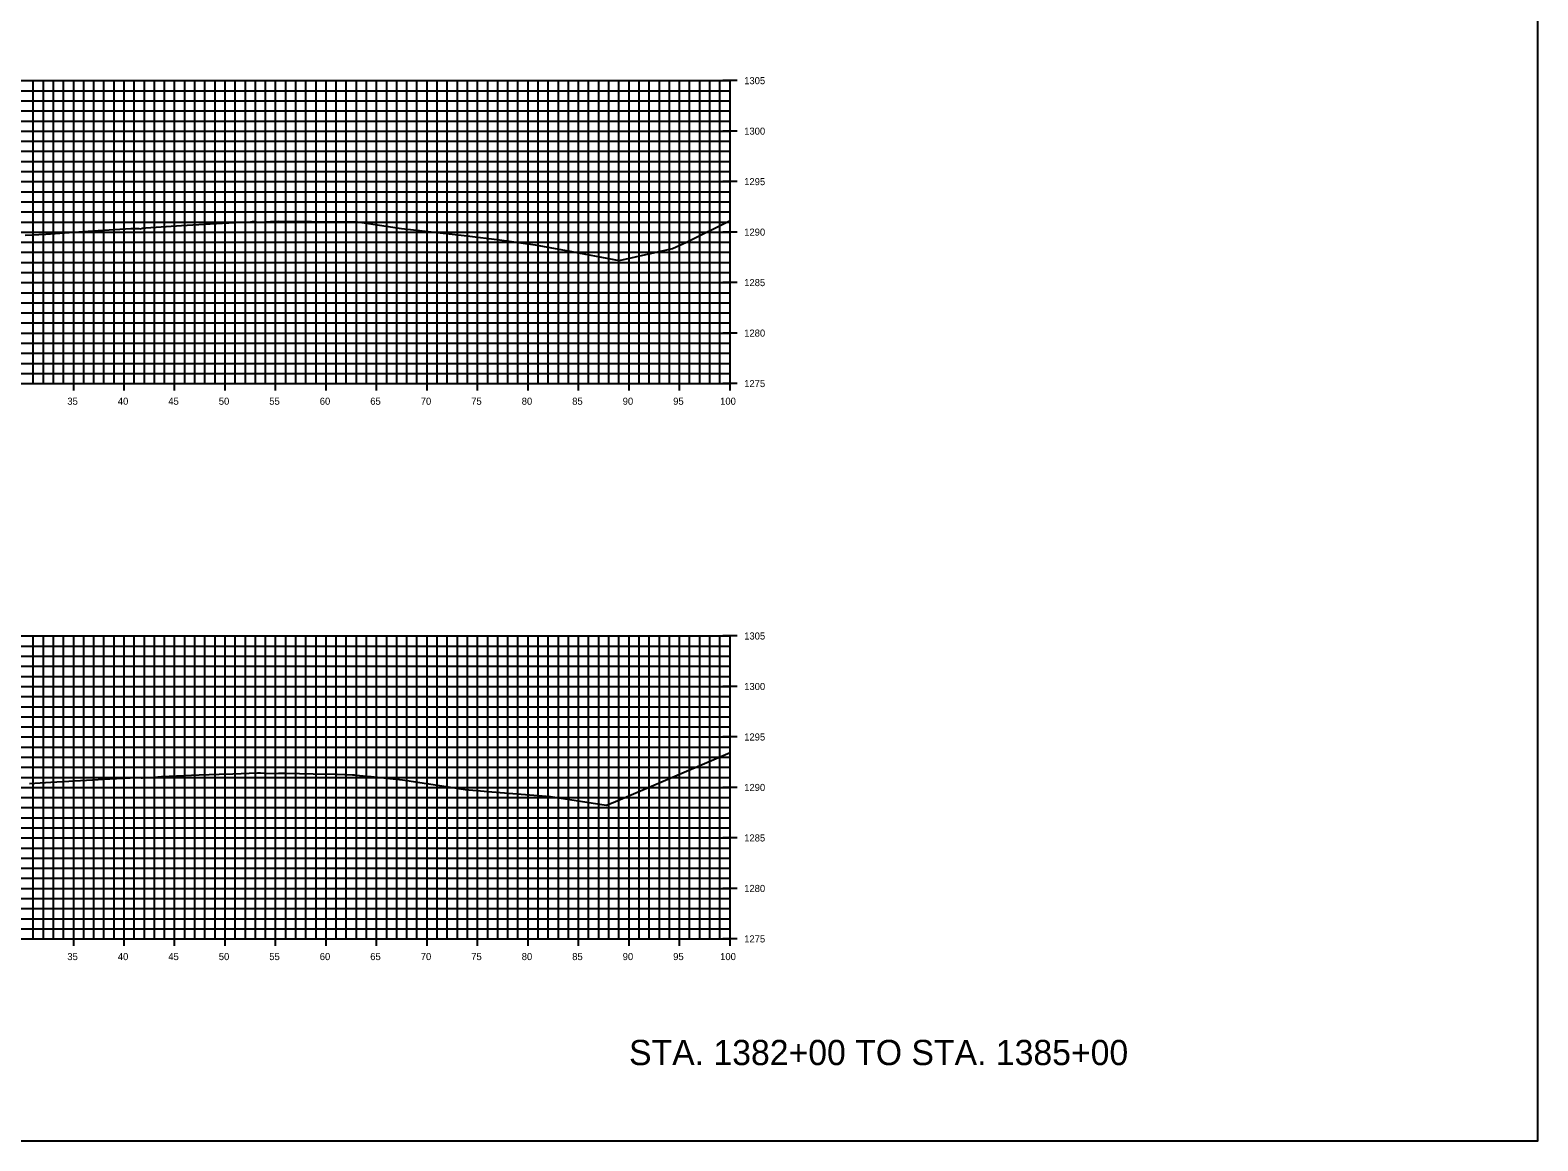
# Model space of a CAD drawing. Extents: x 674939 to 678919, y 750652 to 765176.
# Drawn here: x 678769.2 to 678918.5, y 755292.6 to 755402.6 of the extents above; entities that cross this region are included whole.
import ezdxf

# ---------------------------------------------------------------- set-up
doc = ezdxf.new("R2010")
doc.units = 0
for name, color, linetype in [('R_Axis', 7, 'Continuous'), ('R_Axis Annot', 7, 'Continuous'), ('R_Draft', 7, 'Continuous'), ('R_Exist Surface', 7, 'Continuous'), ('R_Grid', 7, 'Continuous'), ('R_No Plot', 7, 'Continuous')]:
    doc.layers.add(name, color=color, linetype=linetype)

msp = doc.modelspace()

# ---------------------------------------------------------------- linework, layer by layer
at = {"layer": 'R_Axis'}
for p, q in [((678839.23, 755397.55), (678837.83, 755397.55)), ((678838.53, 755367.55), (678838.53, 755397.55)), ((678839.23, 755392.55), (678837.83, 755392.55)), ((678839.23, 755387.55), (678837.83, 755387.55)), ((678839.23, 755382.55), (678837.83, 755382.55)), ((678839.23, 755377.55), (678837.83, 755377.55)), ((678839.23, 755372.55), (678837.83, 755372.55)), ((678638.53, 755367.55), (678838.53, 755367.55)), ((678773.53, 755366.85), (678773.53, 755368.25)), ((678778.53, 755366.85), (678778.53, 755368.25)), ((678783.53, 755366.85), (678783.53, 755368.25)), ((678788.53, 755366.85), (678788.53, 755368.25)), ((678793.53, 755366.85), (678793.53, 755368.25)), ((678798.53, 755366.85), (678798.53, 755368.25)), ((678803.53, 755366.85), (678803.53, 755368.25)), ((678808.53, 755366.85), (678808.53, 755368.25)), ((678813.53, 755366.85), (678813.53, 755368.25)), ((678818.53, 755366.85), (678818.53, 755368.25)), ((678823.53, 755366.85), (678823.53, 755368.25)), ((678828.53, 755366.85), (678828.53, 755368.25)), ((678833.53, 755366.85), (678833.53, 755368.25)), ((678839.23, 755367.55), (678837.83, 755367.55)), ((678838.53, 755366.85), (678838.53, 755368.25)), ((678839.23, 755342.55), (678837.83, 755342.55)), ((678838.53, 755312.55), (678838.53, 755342.55)), ((678839.23, 755337.55), (678837.83, 755337.55)), ((678839.23, 755332.55), (678837.83, 755332.55)), ((678839.23, 755327.55), (678837.83, 755327.55)), ((678839.23, 755322.55), (678837.83, 755322.55)), ((678839.23, 755317.55), (678837.83, 755317.55)), ((678638.53, 755312.55), (678838.53, 755312.55)), ((678773.53, 755311.85), (678773.53, 755313.25)), ((678778.53, 755311.85), (678778.53, 755313.25)), ((678783.53, 755311.85), (678783.53, 755313.25)), ((678788.53, 755311.85), (678788.53, 755313.25)), ((678793.53, 755311.85), (678793.53, 755313.25)), ((678798.53, 755311.85), (678798.53, 755313.25)), ((678803.53, 755311.85), (678803.53, 755313.25)), ((678808.53, 755311.85), (678808.53, 755313.25)), ((678813.53, 755311.85), (678813.53, 755313.25)), ((678818.53, 755311.85), (678818.53, 755313.25)), ((678823.53, 755311.85), (678823.53, 755313.25)), ((678828.53, 755311.85), (678828.53, 755313.25)), ((678833.53, 755311.85), (678833.53, 755313.25)), ((678839.23, 755312.55), (678837.83, 755312.55)), ((678838.53, 755311.85), (678838.53, 755313.25))]:
    msp.add_line(p, q, dxfattribs=at)
at = {"layer": 'R_Exist Surface'}
for points in [[(678768.72, 755382.24), (678770.09, 755382.32), (678770.77, 755382.36), (678775.43, 755382.66), (678779.19, 755382.9), (678779.53, 755382.9), (678779.99, 755382.9), (678780.1, 755382.89), (678780.33, 755382.94), (678780.67, 755382.97), (678784.22, 755383.19), (678787.04, 755383.36), (678789.53, 755383.49), (678791.06, 755383.58), (678791.23, 755383.59), (678791.39, 755383.59), (678791.64, 755383.57), (678791.99, 755383.55), (678793.02, 755383.59), (678793.79, 755383.62), (678797.08, 755383.59), (678801.64, 755383.56), (678804.48, 755383.13), (678805.99, 755382.9), (678810.12, 755382.45), (678812.5, 755382.19), (678815.69, 755381.78), (678819.23, 755381.3), (678822.29, 755380.74), (678827.54, 755379.75), (678832.7, 755380.89), (678832.83, 755380.92), (678834.22, 755381.57), (678838.53, 755383.71)], [(678769.15, 755327.95), (678771.28, 755328.07), (678775.41, 755328.3), (678777.12, 755328.39), (678779.82, 755328.53), (678780.21, 755328.51), (678780.35, 755328.5), (678781.51, 755328.58), (678782.22, 755328.63), (678785.95, 755328.79), (678787.95, 755328.86), (678789.3, 755328.9), (678791.73, 755328.99), (678791.87, 755328.99), (678792.02, 755329), (678792.41, 755328.96), (678792.55, 755328.94), (678793.83, 755328.96), (678794.55, 755328.97), (678797.24, 755328.91), (678799.61, 755328.85), (678801.15, 755328.81), (678801.31, 755328.79), (678801.45, 755328.78), (678802.99, 755328.62), (678806.11, 755328.31), (678810.86, 755327.57), (678812.29, 755327.34), (678814.93, 755327.13), (678820.76, 755326.65), (678825.85, 755325.86), (678826.29, 755325.79), (678827.18, 755326.17), (678830.97, 755327.78), (678838.53, 755331)]]:
    msp.add_lwpolyline(points, dxfattribs=at)
at = {"layer": 'R_Grid'}
for p, q in [((678638.53, 755397.55), (678838.53, 755397.55)), ((678769.53, 755367.55), (678769.53, 755397.55)), ((678770.53, 755367.55), (678770.53, 755397.55)), ((678771.53, 755367.55), (678771.53, 755397.55)), ((678772.53, 755367.55), (678772.53, 755397.55)), ((678773.53, 755367.55), (678773.53, 755397.55)), ((678774.53, 755367.55), (678774.53, 755397.55)), ((678775.53, 755367.55), (678775.53, 755397.55)), ((678776.53, 755367.55), (678776.53, 755397.55)), ((678777.53, 755367.55), (678777.53, 755397.55)), ((678778.53, 755367.55), (678778.53, 755397.55)), ((678779.53, 755367.55), (678779.53, 755397.55)), ((678780.53, 755367.55), (678780.53, 755397.55)), ((678781.53, 755367.55), (678781.53, 755397.55)), ((678782.53, 755367.55), (678782.53, 755397.55)), ((678783.53, 755367.55), (678783.53, 755397.55)), ((678784.53, 755367.55), (678784.53, 755397.55)), ((678785.53, 755367.55), (678785.53, 755397.55)), ((678786.53, 755367.55), (678786.53, 755397.55)), ((678787.53, 755367.55), (678787.53, 755397.55)), ((678788.53, 755367.55), (678788.53, 755397.55)), ((678789.53, 755367.55), (678789.53, 755397.55)), ((678790.53, 755367.55), (678790.53, 755397.55)), ((678791.53, 755367.55), (678791.53, 755397.55)), ((678792.53, 755367.55), (678792.53, 755397.55)), ((678793.53, 755367.55), (678793.53, 755397.55)), ((678794.53, 755367.55), (678794.53, 755397.55)), ((678795.53, 755367.55), (678795.53, 755397.55)), ((678796.53, 755367.55), (678796.53, 755397.55)), ((678797.53, 755367.55), (678797.53, 755397.55)), ((678798.53, 755367.55), (678798.53, 755397.55)), ((678799.53, 755367.55), (678799.53, 755397.55)), ((678800.53, 755367.55), (678800.53, 755397.55)), ((678801.53, 755367.55), (678801.53, 755397.55)), ((678802.53, 755367.55), (678802.53, 755397.55)), ((678803.53, 755367.55), (678803.53, 755397.55)), ((678804.53, 755367.55), (678804.53, 755397.55)), ((678805.53, 755367.55), (678805.53, 755397.55)), ((678806.53, 755367.55), (678806.53, 755397.55)), ((678807.53, 755367.55), (678807.53, 755397.55)), ((678808.53, 755367.55), (678808.53, 755397.55)), ((678809.53, 755367.55), (678809.53, 755397.55)), ((678810.53, 755367.55), (678810.53, 755397.55)), ((678811.53, 755367.55), (678811.53, 755397.55)), ((678812.53, 755367.55), (678812.53, 755397.55)), ((678813.53, 755367.55), (678813.53, 755397.55)), ((678814.53, 755367.55), (678814.53, 755397.55)), ((678815.53, 755367.55), (678815.53, 755397.55)), ((678816.53, 755367.55), (678816.53, 755397.55)), ((678817.53, 755367.55), (678817.53, 755397.55)), ((678818.53, 755367.55), (678818.53, 755397.55)), ((678819.53, 755367.55), (678819.53, 755397.55)), ((678820.53, 755367.55), (678820.53, 755397.55)), ((678821.53, 755367.55), (678821.53, 755397.55)), ((678822.53, 755367.55), (678822.53, 755397.55)), ((678823.53, 755367.55), (678823.53, 755397.55)), ((678824.53, 755367.55), (678824.53, 755397.55)), ((678825.53, 755367.55), (678825.53, 755397.55)), ((678826.53, 755367.55), (678826.53, 755397.55)), ((678827.53, 755367.55), (678827.53, 755397.55)), ((678828.53, 755367.55), (678828.53, 755397.55)), ((678829.53, 755367.55), (678829.53, 755397.55)), ((678830.53, 755367.55), (678830.53, 755397.55)), ((678831.53, 755367.55), (678831.53, 755397.55)), ((678832.53, 755367.55), (678832.53, 755397.55)), ((678833.53, 755367.55), (678833.53, 755397.55)), ((678834.53, 755367.55), (678834.53, 755397.55)), ((678835.53, 755367.55), (678835.53, 755397.55)), ((678836.53, 755367.55), (678836.53, 755397.55)), ((678837.53, 755367.55), (678837.53, 755397.55)), ((678838.53, 755367.55), (678838.53, 755397.55)), ((678638.53, 755396.55), (678838.53, 755396.55)), ((678638.53, 755395.55), (678838.53, 755395.55)), ((678638.53, 755394.55), (678838.53, 755394.55)), ((678638.53, 755393.55), (678838.53, 755393.55)), ((678638.53, 755392.55), (678838.53, 755392.55)), ((678638.53, 755391.55), (678838.53, 755391.55)), ((678638.53, 755390.55), (678838.53, 755390.55)), ((678638.53, 755389.55), (678838.53, 755389.55)), ((678638.53, 755388.55), (678838.53, 755388.55)), ((678638.53, 755387.55), (678838.53, 755387.55)), ((678638.53, 755386.55), (678838.53, 755386.55)), ((678638.53, 755385.55), (678838.53, 755385.55)), ((678638.53, 755384.55), (678838.53, 755384.55)), ((678638.53, 755383.55), (678838.53, 755383.55)), ((678638.53, 755382.55), (678838.53, 755382.55)), ((678638.53, 755381.55), (678838.53, 755381.55)), ((678638.53, 755380.55), (678838.53, 755380.55)), ((678638.53, 755379.55), (678838.53, 755379.55)), ((678638.53, 755378.55), (678838.53, 755378.55)), ((678638.53, 755377.55), (678838.53, 755377.55)), ((678638.53, 755376.55), (678838.53, 755376.55)), ((678638.53, 755375.55), (678838.53, 755375.55)), ((678638.53, 755374.55), (678838.53, 755374.55)), ((678638.53, 755373.55), (678838.53, 755373.55)), ((678638.53, 755372.55), (678838.53, 755372.55)), ((678638.53, 755371.55), (678838.53, 755371.55)), ((678638.53, 755370.55), (678838.53, 755370.55)), ((678638.53, 755369.55), (678838.53, 755369.55)), ((678638.53, 755368.55), (678838.53, 755368.55)), ((678638.53, 755367.55), (678838.53, 755367.55)), ((678638.53, 755342.55), (678838.53, 755342.55)), ((678769.53, 755312.55), (678769.53, 755342.55)), ((678770.53, 755312.55), (678770.53, 755342.55)), ((678771.53, 755312.55), (678771.53, 755342.55)), ((678772.53, 755312.55), (678772.53, 755342.55)), ((678773.53, 755312.55), (678773.53, 755342.55)), ((678774.53, 755312.55), (678774.53, 755342.55)), ((678775.53, 755312.55), (678775.53, 755342.55)), ((678776.53, 755312.55), (678776.53, 755342.55)), ((678777.53, 755312.55), (678777.53, 755342.55)), ((678778.53, 755312.55), (678778.53, 755342.55)), ((678779.53, 755312.55), (678779.53, 755342.55)), ((678780.53, 755312.55), (678780.53, 755342.55)), ((678781.53, 755312.55), (678781.53, 755342.55)), ((678782.53, 755312.55), (678782.53, 755342.55)), ((678783.53, 755312.55), (678783.53, 755342.55)), ((678784.53, 755312.55), (678784.53, 755342.55)), ((678785.53, 755312.55), (678785.53, 755342.55)), ((678786.53, 755312.55), (678786.53, 755342.55)), ((678787.53, 755312.55), (678787.53, 755342.55)), ((678788.53, 755312.55), (678788.53, 755342.55)), ((678789.53, 755312.55), (678789.53, 755342.55)), ((678790.53, 755312.55), (678790.53, 755342.55)), ((678791.53, 755312.55), (678791.53, 755342.55)), ((678792.53, 755312.55), (678792.53, 755342.55)), ((678793.53, 755312.55), (678793.53, 755342.55)), ((678794.53, 755312.55), (678794.53, 755342.55)), ((678795.53, 755312.55), (678795.53, 755342.55)), ((678796.53, 755312.55), (678796.53, 755342.55)), ((678797.53, 755312.55), (678797.53, 755342.55)), ((678798.53, 755312.55), (678798.53, 755342.55)), ((678799.53, 755312.55), (678799.53, 755342.55)), ((678800.53, 755312.55), (678800.53, 755342.55)), ((678801.53, 755312.55), (678801.53, 755342.55)), ((678802.53, 755312.55), (678802.53, 755342.55)), ((678803.53, 755312.55), (678803.53, 755342.55)), ((678804.53, 755312.55), (678804.53, 755342.55)), ((678805.53, 755312.55), (678805.53, 755342.55)), ((678806.53, 755312.55), (678806.53, 755342.55)), ((678807.53, 755312.55), (678807.53, 755342.55)), ((678808.53, 755312.55), (678808.53, 755342.55)), ((678809.53, 755312.55), (678809.53, 755342.55)), ((678810.53, 755312.55), (678810.53, 755342.55)), ((678811.53, 755312.55), (678811.53, 755342.55)), ((678812.53, 755312.55), (678812.53, 755342.55)), ((678813.53, 755312.55), (678813.53, 755342.55)), ((678814.53, 755312.55), (678814.53, 755342.55)), ((678815.53, 755312.55), (678815.53, 755342.55)), ((678816.53, 755312.55), (678816.53, 755342.55)), ((678817.53, 755312.55), (678817.53, 755342.55)), ((678818.53, 755312.55), (678818.53, 755342.55)), ((678819.53, 755312.55), (678819.53, 755342.55)), ((678820.53, 755312.55), (678820.53, 755342.55)), ((678821.53, 755312.55), (678821.53, 755342.55)), ((678822.53, 755312.55), (678822.53, 755342.55)), ((678823.53, 755312.55), (678823.53, 755342.55)), ((678824.53, 755312.55), (678824.53, 755342.55)), ((678825.53, 755312.55), (678825.53, 755342.55)), ((678826.53, 755312.55), (678826.53, 755342.55)), ((678827.53, 755312.55), (678827.53, 755342.55)), ((678828.53, 755312.55), (678828.53, 755342.55)), ((678829.53, 755312.55), (678829.53, 755342.55)), ((678830.53, 755312.55), (678830.53, 755342.55)), ((678831.53, 755312.55), (678831.53, 755342.55)), ((678832.53, 755312.55), (678832.53, 755342.55)), ((678833.53, 755312.55), (678833.53, 755342.55)), ((678834.53, 755312.55), (678834.53, 755342.55)), ((678835.53, 755312.55), (678835.53, 755342.55)), ((678836.53, 755312.55), (678836.53, 755342.55)), ((678837.53, 755312.55), (678837.53, 755342.55)), ((678838.53, 755312.55), (678838.53, 755342.55)), ((678638.53, 755341.55), (678838.53, 755341.55)), ((678638.53, 755340.55), (678838.53, 755340.55)), ((678638.53, 755339.55), (678838.53, 755339.55)), ((678638.53, 755338.55), (678838.53, 755338.55)), ((678638.53, 755337.55), (678838.53, 755337.55)), ((678638.53, 755336.55), (678838.53, 755336.55)), ((678638.53, 755335.55), (678838.53, 755335.55)), ((678638.53, 755334.55), (678838.53, 755334.55)), ((678638.53, 755333.55), (678838.53, 755333.55)), ((678638.53, 755332.55), (678838.53, 755332.55)), ((678638.53, 755331.55), (678838.53, 755331.55)), ((678638.53, 755330.55), (678838.53, 755330.55)), ((678638.53, 755329.55), (678838.53, 755329.55)), ((678638.53, 755328.55), (678838.53, 755328.55)), ((678638.53, 755327.55), (678838.53, 755327.55)), ((678638.53, 755326.55), (678838.53, 755326.55)), ((678638.53, 755325.55), (678838.53, 755325.55)), ((678638.53, 755324.55), (678838.53, 755324.55)), ((678638.53, 755323.55), (678838.53, 755323.55)), ((678638.53, 755322.55), (678838.53, 755322.55)), ((678638.53, 755321.55), (678838.53, 755321.55)), ((678638.53, 755320.55), (678838.53, 755320.55)), ((678638.53, 755319.55), (678838.53, 755319.55)), ((678638.53, 755318.55), (678838.53, 755318.55)), ((678638.53, 755317.55), (678838.53, 755317.55)), ((678638.53, 755316.55), (678838.53, 755316.55)), ((678638.53, 755315.55), (678838.53, 755315.55)), ((678638.53, 755314.55), (678838.53, 755314.55)), ((678638.53, 755313.55), (678838.53, 755313.55)), ((678638.53, 755312.55), (678838.53, 755312.55))]:
    msp.add_line(p, q, dxfattribs=at)
at = {"layer": 'R_No Plot'}
msp.add_lwpolyline([(678578.53, 755292.55), (678918.53, 755292.55), (678918.53, 755512.55), (678578.53, 755512.55)], close=True, dxfattribs=at)

# ---------------------------------------------------------------- texts
at = {"layer": 'R_Axis Annot'}
for s, p in [('1305', (678839.93, 755397.2)), ('1300', (678839.93, 755392.2)), ('1295', (678839.93, 755387.2)), ('1290', (678839.93, 755382.2)), ('1285', (678839.93, 755377.2)), ('1280', (678839.93, 755372.2)), ('1275', (678839.93, 755367.2)), ('35', (678772.9, 755365.45)), ('40', (678777.9, 755365.45)), ('45', (678782.9, 755365.45)), ('50', (678787.9, 755365.45)), ('55', (678792.9, 755365.45)), ('60', (678797.9, 755365.45)), ('65', (678802.9, 755365.45)), ('70', (678807.9, 755365.45)), ('75', (678812.9, 755365.45)), ('80', (678817.9, 755365.45)), ('85', (678822.9, 755365.45)), ('90', (678827.9, 755365.45)), ('95', (678832.9, 755365.45)), ('100', (678837.55, 755365.45)), ('1305', (678839.93, 755342.2)), ('1300', (678839.93, 755337.2)), ('1295', (678839.93, 755332.2)), ('1290', (678839.93, 755327.2)), ('1285', (678839.93, 755322.2)), ('1280', (678839.93, 755317.2)), ('1275', (678839.93, 755312.2)), ('35', (678772.9, 755310.45)), ('40', (678777.9, 755310.45)), ('45', (678782.9, 755310.45)), ('50', (678787.9, 755310.45)), ('55', (678792.9, 755310.45)), ('60', (678797.9, 755310.45)), ('65', (678802.9, 755310.45)), ('70', (678807.9, 755310.45)), ('75', (678812.9, 755310.45)), ('80', (678817.9, 755310.45)), ('85', (678822.9, 755310.45)), ('90', (678827.9, 755310.45)), ('95', (678832.9, 755310.45)), ('100', (678837.55, 755310.45))]:
    msp.add_text(s, height=0.7, dxfattribs=at).set_placement(p)
at = {"layer": 'R_Draft'}
msp.add_text('STA. 1382+00 TO STA. 1385+00', height=2.5, dxfattribs=at).set_placement((678828.53, 755300.05))

doc.saveas('drawing.dxf')
